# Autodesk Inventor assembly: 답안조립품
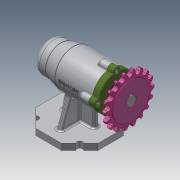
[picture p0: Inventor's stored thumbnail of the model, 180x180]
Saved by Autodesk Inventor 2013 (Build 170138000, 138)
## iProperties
Created: 2021-01
Part Number: 답안조립품
Document SubType Name: Assembly
Designer: a
Author: a
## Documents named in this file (12)
- C:\Users\a\Desktop\710106V1003\답안조립품.iam
- C:\Users\a\Desktop\710106V1003\본체.ipt
- C:\Users\a\Desktop\710106V1003\멈춤나사 M3.ipt
- C:\Users\a\Desktop\710106V1003\베어링 6004.ipt
- C:\Users\a\Desktop\710106V1003\베어링 51202.ipt
- C:\Users\a\Desktop\710106V1003\볼트 M4.ipt
- C:\Users\a\Desktop\710106V1003\스프로킷.ipt
- C:\Users\a\Desktop\710106V1003\어댑터슬리브.ipt
- C:\Users\a\Desktop\710106V1003\오일 실.ipt
- C:\Users\a\Desktop\710106V1003\축.ipt
- C:\Users\a\Desktop\710106V1003\커버.ipt
- C:\Users\a\Desktop\710106V1003\키 5 x 5 x 14.ipt
